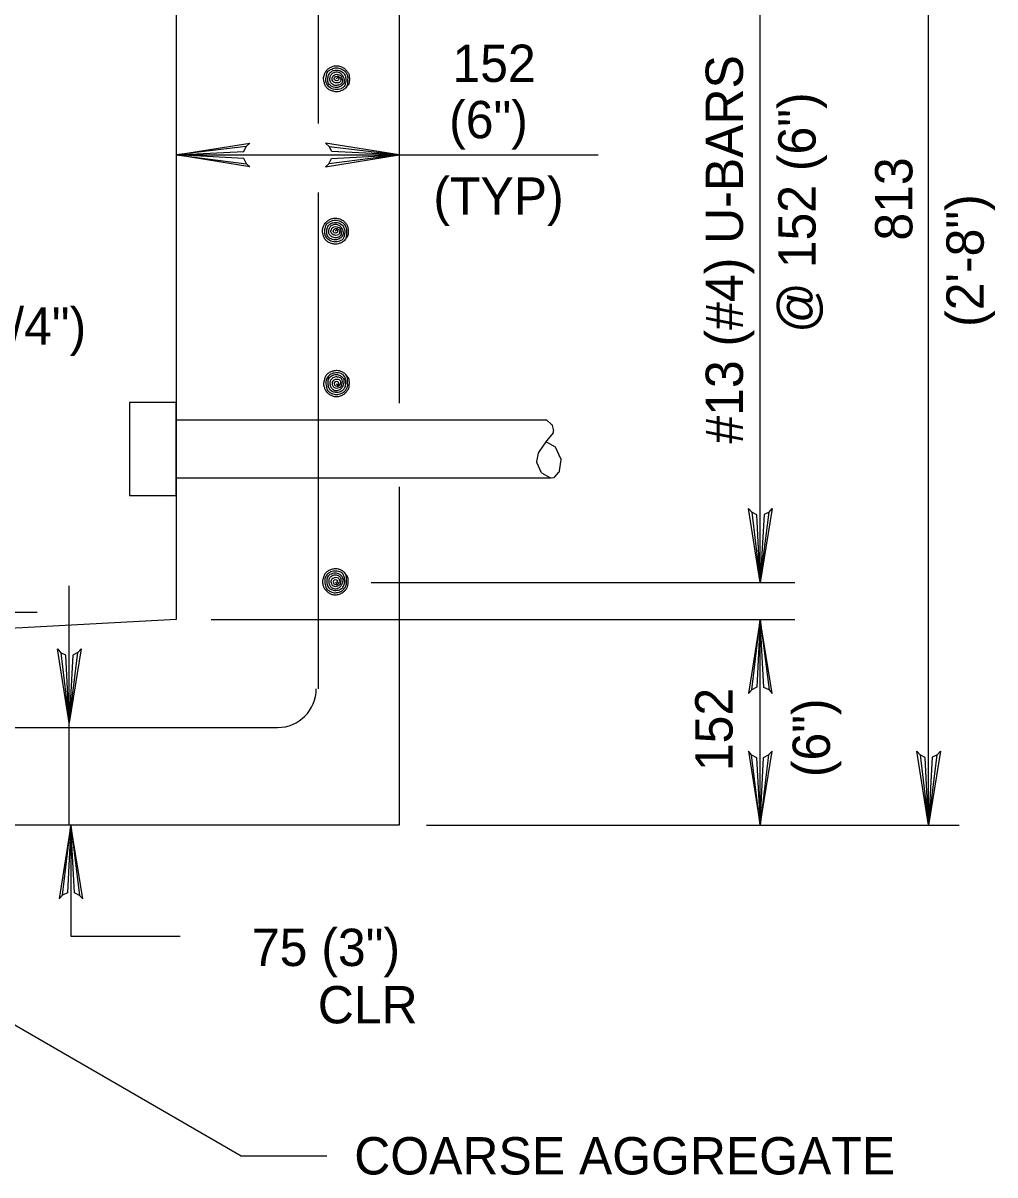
# Model space of a CAD drawing. Extents: x 638455 to 640199, y 298558 to 299152.
# Drawn here: x 638702.3 to 638789.8, y 298665.5 to 298769.2 of the extents above; entities that cross this region are included whole.
import ezdxf

# ---------------------------------------------------------------- set-up
doc = ezdxf.new("R2010")
doc.units = 0
for name, color, linetype in [('1', 7, 'Continuous'), ('2', 7, 'Continuous'), ('3', 7, 'Continuous')]:
    doc.layers.add(name, color=color, linetype=linetype)

msp = doc.modelspace()

# ---------------------------------------------------------------- linework, layer by layer
at = {"layer": '1'}
for p, q in [((638749.47, 298733.51), (638749.93, 298733.1)), ((638749.99, 298732.99), (638750.11, 298732.53)), ((638750.07, 298732.35), (638749.49, 298731.64)), ((638749.48, 298731.63), (638748.75, 298730.57)), ((638750.22, 298731.09), (638749.43, 298731.53)), ((638750.77, 298730.01), (638750.31, 298731)), ((638748.72, 298730.5), (638748.56, 298729.75)), ((638750.63, 298728.91), (638750.79, 298729.9)), ((638748.58, 298729.63), (638748.94, 298728.84)), ((638750.22, 298728.38), (638750.59, 298728.81)), ((638749.02, 298728.75), (638749.77, 298728.32)), ((638749.9, 298728.29), (638750.1, 298728.31))]:
    msp.add_line(p, q, dxfattribs=at)
for centre, start, end in [((638749.8, 298732.95), 13.5634, 48.2002), ((638749.91, 298732.48), 320.9795, 13.5634), ((638749.65, 298731.52), 140.9795, 145.5535), ((638750.13, 298730.91), 25.1893, 60.8708), ((638748.92, 298730.46), 145.5535, 167.862), ((638750.59, 298729.93), 351.1749, 25.1893), ((638748.76, 298729.71), 167.862, 204.893), ((638749.12, 298728.93), 204.893, 239.5523), ((638750.44, 298728.94), 319.4139, 351.1749), ((638749.87, 298728.49), 239.5523, 277.1288), ((638750.07, 298728.51), 277.1288, 319.4139)]:
    msp.add_arc(centre, 0.2, start, end, dxfattribs=at)
at = {"layer": '2'}
for p, q in [((638736.21, 298798.33), (638736.21, 298735)), ((638783.84, 298697.04), (638783.84, 298798.33)), ((638728.9, 298792.41), (638728.9, 298760.17)), ((638768.71, 298718.88), (638768.71, 298791.5)), ((638716.12, 298786.65), (638716.12, 298715.53)), ((638716.12, 298757.35), (638736.21, 298757.35)), ((638736.21, 298757.35), (638754.11, 298757.35)), ((638728.9, 298753.96), (638728.9, 298709.3)), ((638716.12, 298733.5), (638749.47, 298733.5)), ((638716.12, 298728.28), (638749.87, 298728.28)), ((638716.12, 298727.41), (638716.12, 298727.41)), ((638716.12, 298726.71), (638716.12, 298726.71)), ((638736.21, 298727.49), (638736.21, 298697.04)), ((638706.5, 298697.04), (638706.5, 298718.56)), ((638733.69, 298718.88), (638771.81, 298718.88)), ((638642.17, 298716.21), (638703.62, 298716.21)), ((638716.12, 298715.53), (638680.69, 298713.62)), ((638719.27, 298715.53), (638771.81, 298715.53)), ((638768.71, 298697.04), (638768.71, 298715.53)), ((638621.25, 298705.81), (638725.26, 298705.81)), ((638736.21, 298697.04), (638610.59, 298697.04)), ((638706.65, 298697.04), (638706.65, 298687.03)), ((638738.65, 298697.04), (638786.6, 298697.04)), ((638721.98, 298667.25), (638685.64, 298688.24)), ((638706.65, 298687.03), (638716.5, 298687.03)), ((638729.7, 298667.25), (638721.98, 298667.25))]:
    msp.add_line(p, q, dxfattribs=at)
for points in [[(638722.45, 298756.56), (638722.21, 298757.02), (638716.12, 298757.35), (638722.45, 298756.56), (638722.77, 298756.28), (638716.12, 298757.35), (638722.21, 298757.65), (638722.43, 298758.11), (638716.12, 298757.35), (638722.77, 298758.41), (638722.43, 298758.11)], [(638729.88, 298756.56), (638730.12, 298757.02), (638736.21, 298757.35), (638729.88, 298756.56), (638729.56, 298756.28), (638736.21, 298757.35), (638730.13, 298757.65), (638729.9, 298758.11), (638736.21, 298757.35), (638729.56, 298758.41), (638729.9, 298758.11)], [(638769.5, 298725.21), (638769.05, 298724.98), (638768.71, 298718.88), (638769.5, 298725.21), (638769.78, 298725.54), (638768.71, 298718.88), (638768.41, 298724.97), (638767.95, 298725.19), (638768.71, 298718.88), (638767.65, 298725.54), (638767.95, 298725.19)], [(638769.5, 298709.2), (638769.04, 298709.43), (638768.71, 298715.53), (638769.5, 298709.2), (638769.78, 298708.87), (638768.71, 298715.53), (638768.41, 298709.44), (638767.95, 298709.22), (638768.71, 298715.53), (638767.65, 298708.87), (638767.95, 298709.22)], [(638707.29, 298712.57), (638706.83, 298712.34), (638706.5, 298706.24), (638707.29, 298712.57), (638707.57, 298712.9), (638706.5, 298706.24), (638706.19, 298712.33), (638705.74, 298712.55), (638706.5, 298706.24), (638705.44, 298712.9), (638705.74, 298712.55)], [(638767.91, 298703.37), (638768.37, 298703.13), (638768.71, 298697.04), (638767.91, 298703.37), (638767.64, 298703.69), (638768.71, 298697.04), (638769.01, 298703.13), (638769.46, 298703.35), (638768.71, 298697.04), (638769.77, 298703.69), (638769.46, 298703.35)], [(638784.64, 298703.37), (638784.18, 298703.14), (638783.84, 298697.04), (638784.64, 298703.37), (638784.92, 298703.7), (638783.84, 298697.04), (638783.54, 298703.13), (638783.09, 298703.35), (638783.84, 298697.04), (638782.79, 298703.7), (638783.09, 298703.35)], [(638707.44, 298690.71), (638706.98, 298690.95), (638706.65, 298697.04), (638707.44, 298690.71), (638707.72, 298690.39), (638706.65, 298697.04), (638706.34, 298690.95), (638705.89, 298690.73), (638706.65, 298697.04), (638705.59, 298690.39), (638705.89, 298690.73)]]:
    msp.add_lwpolyline(points, dxfattribs=at)
msp.add_lwpolyline([(638716.12, 298726.71), (638716.12, 298735.07), (638711.93, 298735.07), (638711.93, 298726.71)], close=True, dxfattribs=at)
msp.add_arc((638725.26, 298709.3), 3.48, 270, 0, dxfattribs=at)
for points in [[(638730.57, 298764.2), (638730.63, 298764.32), (638730.72, 298764.3), (638730.74, 298764.12), (638730.58, 298764.02), (638730.38, 298764.12), (638730.39, 298764.3), (638730.5, 298764.42), (638730.72, 298764.43), (638730.87, 298764.32), (638730.95, 298764.13), (638730.84, 298763.88), (638730.6, 298763.83), (638730.33, 298763.9), (638730.18, 298764.08), (638730.2, 298764.36), (638730.34, 298764.54), (638730.58, 298764.61), (638730.79, 298764.57), (638730.97, 298764.46), (638731.05, 298764.27), (638731.09, 298764.03), (638731.04, 298763.81), (638730.83, 298763.67), (638730.5, 298763.6), (638730.16, 298763.74), (638729.98, 298763.99), (638729.98, 298764.32), (638730.1, 298764.6), (638730.34, 298764.78), (638730.72, 298764.81), (638730.99, 298764.66), (638731.16, 298764.39), (638731.25, 298764.12), (638731.21, 298763.79), (638730.99, 298763.56), (638730.67, 298763.43), (638730.17, 298763.5), (638729.85, 298763.78), (638729.79, 298764.17), (638729.85, 298764.54), (638730.07, 298764.84), (638730.37, 298764.96), (638730.83, 298764.95), (638731.19, 298764.74), (638731.36, 298764.43), (638731.41, 298764.11), (638731.37, 298763.83), (638731.26, 298763.52), (638730.97, 298763.31), (638730.49, 298763.24), (638730.06, 298763.36), (638729.74, 298763.66), (638729.61, 298764), (638729.65, 298764.44), (638729.79, 298764.86), (638730.03, 298765.03), (638730.45, 298765.19), (638730.89, 298765.12), (638731.2, 298764.98), (638731.44, 298764.71), (638731.56, 298764.42), (638731.56, 298764.12), (638731.55, 298763.79), (638731.47, 298763.48), (638731.32, 298763.31), (638731.08, 298763.16), (638730.84, 298763.07), (638730.6, 298763.03), (638730.29, 298763.08), (638729.98, 298763.18), (638729.72, 298763.37), (638729.54, 298763.62), (638729.45, 298763.93), (638729.4, 298764.23), (638729.47, 298764.57), (638729.59, 298764.84), (638729.81, 298765.09), (638730.07, 298765.26), (638730.34, 298765.36), (638730.65, 298765.37), (638731.01, 298765.28), (638731.32, 298765.09), (638731.5, 298764.89), (638731.66, 298764.64), (638731.71, 298764.38), (638731.72, 298764.08), (638731.66, 298763.74), (638731.56, 298763.59), (638731.36, 298763.37)], [(638730.47, 298750.49), (638730.53, 298750.6), (638730.62, 298750.59), (638730.64, 298750.41), (638730.48, 298750.31), (638730.28, 298750.41), (638730.29, 298750.59), (638730.4, 298750.7), (638730.62, 298750.72), (638730.77, 298750.6), (638730.85, 298750.42), (638730.73, 298750.17), (638730.49, 298750.11), (638730.23, 298750.19), (638730.08, 298750.36), (638730.1, 298750.65), (638730.23, 298750.83), (638730.48, 298750.9), (638730.69, 298750.85), (638730.87, 298750.75), (638730.95, 298750.56), (638730.99, 298750.32), (638730.93, 298750.1), (638730.73, 298749.95), (638730.41, 298749.89), (638730.06, 298750.04), (638729.88, 298750.28), (638729.88, 298750.6), (638729.99, 298750.89), (638730.23, 298751.07), (638730.62, 298751.1), (638730.89, 298750.94), (638731.06, 298750.68), (638731.16, 298750.41), (638731.11, 298750.08), (638730.89, 298749.85), (638730.57, 298749.71), (638730.07, 298749.79), (638729.75, 298750.07), (638729.69, 298750.45), (638729.75, 298750.83), (638729.97, 298751.13), (638730.27, 298751.25), (638730.73, 298751.24), (638731.09, 298751.03), (638731.26, 298750.72), (638731.31, 298750.4), (638731.27, 298750.11), (638731.16, 298749.81), (638730.87, 298749.6), (638730.39, 298749.53), (638729.96, 298749.65), (638729.64, 298749.95), (638729.51, 298750.29), (638729.54, 298750.74), (638729.69, 298751.15), (638729.93, 298751.32), (638730.35, 298751.48), (638730.79, 298751.41), (638731.1, 298751.27), (638731.34, 298751), (638731.46, 298750.71), (638731.46, 298750.41), (638731.45, 298750.08), (638731.37, 298749.77), (638731.22, 298749.6), (638730.98, 298749.45), (638730.73, 298749.36), (638730.49, 298749.32), (638730.19, 298749.36), (638729.88, 298749.46), (638729.62, 298749.66), (638729.44, 298749.91), (638729.35, 298750.22), (638729.3, 298750.52), (638729.37, 298750.85), (638729.49, 298751.13), (638729.71, 298751.38), (638729.97, 298751.55), (638730.23, 298751.64), (638730.55, 298751.65), (638730.91, 298751.57), (638731.22, 298751.38), (638731.41, 298751.18), (638731.56, 298750.93), (638731.61, 298750.67), (638731.62, 298750.36), (638731.56, 298750.04), (638731.46, 298749.88), (638731.26, 298749.66)], [(638730.57, 298736.77), (638730.63, 298736.66), (638730.72, 298736.67), (638730.74, 298736.86), (638730.58, 298736.95), (638730.38, 298736.86), (638730.39, 298736.67), (638730.5, 298736.56), (638730.72, 298736.54), (638730.87, 298736.66), (638730.95, 298736.85), (638730.84, 298737.1), (638730.6, 298737.15), (638730.33, 298737.07), (638730.18, 298736.9), (638730.2, 298736.62), (638730.34, 298736.43), (638730.58, 298736.37), (638730.79, 298736.41), (638730.97, 298736.52), (638731.05, 298736.7), (638731.09, 298736.95), (638731.04, 298737.17), (638730.83, 298737.31), (638730.5, 298737.37), (638730.16, 298737.23), (638729.98, 298736.99), (638729.98, 298736.66), (638730.1, 298736.38), (638730.34, 298736.19), (638730.72, 298736.17), (638730.99, 298736.32), (638731.16, 298736.58), (638731.25, 298736.86), (638731.21, 298737.19), (638730.99, 298737.42), (638730.67, 298737.55), (638730.17, 298737.47), (638729.85, 298737.2), (638729.79, 298736.81), (638729.85, 298736.43), (638730.07, 298736.14), (638730.37, 298736.02), (638730.83, 298736.03), (638731.19, 298736.23), (638731.36, 298736.54), (638731.41, 298736.87), (638731.37, 298737.15), (638731.26, 298737.45), (638730.97, 298737.67), (638730.49, 298737.74), (638730.06, 298737.61), (638729.74, 298737.32), (638729.61, 298736.97), (638729.65, 298736.53), (638729.79, 298736.12), (638730.03, 298735.94), (638730.45, 298735.79), (638730.89, 298735.85), (638731.2, 298736), (638731.44, 298736.27), (638731.56, 298736.55), (638731.56, 298736.86), (638731.55, 298737.19), (638731.47, 298737.49), (638731.32, 298737.67), (638731.08, 298737.82), (638730.84, 298737.91), (638730.6, 298737.94), (638730.29, 298737.9), (638729.98, 298737.8), (638729.72, 298737.61), (638729.54, 298737.36), (638729.45, 298737.04), (638729.4, 298736.75), (638729.47, 298736.41), (638729.59, 298736.14), (638729.81, 298735.89), (638730.07, 298735.72), (638730.34, 298735.62), (638730.65, 298735.61), (638731.01, 298735.7), (638731.32, 298735.89), (638731.5, 298736.08), (638731.66, 298736.33), (638731.71, 298736.6), (638731.72, 298736.9), (638731.66, 298737.23), (638731.56, 298737.38), (638731.36, 298737.61)], [(638730.47, 298718.94), (638730.53, 298718.82), (638730.62, 298718.83), (638730.64, 298719.01), (638730.48, 298719.11), (638730.28, 298719.01), (638730.29, 298718.83), (638730.4, 298718.72), (638730.62, 298718.7), (638730.77, 298718.82), (638730.85, 298719), (638730.73, 298719.25), (638730.49, 298719.31), (638730.23, 298719.23), (638730.08, 298719.06), (638730.1, 298718.77), (638730.23, 298718.59), (638730.48, 298718.52), (638730.69, 298718.57), (638730.87, 298718.68), (638730.95, 298718.86), (638730.99, 298719.1), (638730.93, 298719.33), (638730.73, 298719.47), (638730.41, 298719.53), (638730.06, 298719.39), (638729.88, 298719.15), (638729.88, 298718.82), (638729.99, 298718.54), (638730.23, 298718.35), (638730.62, 298718.33), (638730.89, 298718.48), (638731.06, 298718.74), (638731.16, 298719.01), (638731.11, 298719.34), (638730.89, 298719.58), (638730.57, 298719.71), (638730.07, 298719.63), (638729.75, 298719.35), (638729.69, 298718.97), (638729.75, 298718.59), (638729.97, 298718.3), (638730.27, 298718.18), (638730.73, 298718.19), (638731.09, 298718.39), (638731.26, 298718.7), (638731.31, 298719.03), (638731.27, 298719.31), (638731.16, 298719.61), (638730.87, 298719.83), (638730.39, 298719.89), (638729.96, 298719.77), (638729.64, 298719.48), (638729.51, 298719.13), (638729.54, 298718.69), (638729.69, 298718.27), (638729.93, 298718.1), (638730.35, 298717.95), (638730.79, 298718.01), (638731.1, 298718.15), (638731.34, 298718.43), (638731.46, 298718.71), (638731.46, 298719.01), (638731.45, 298719.34), (638731.37, 298719.65), (638731.22, 298719.83), (638730.98, 298719.98), (638730.73, 298720.07), (638730.49, 298720.1), (638730.19, 298720.06), (638729.88, 298719.96), (638729.62, 298719.76), (638729.44, 298719.51), (638729.35, 298719.2), (638729.3, 298718.91), (638729.37, 298718.57), (638729.49, 298718.3), (638729.71, 298718.05), (638729.97, 298717.88), (638730.23, 298717.78), (638730.55, 298717.77), (638730.91, 298717.86), (638731.22, 298718.05), (638731.41, 298718.24), (638731.56, 298718.49), (638731.61, 298718.75), (638731.62, 298719.06), (638731.56, 298719.39), (638731.46, 298719.54), (638731.26, 298719.76)]]:
    msp.add_spline(points, degree=3, dxfattribs=at)

# ---------------------------------------------------------------- texts
at = {"layer": '3'}
for s, p in [('152', (638741, 298763.92)), ('(6")', (638740.7, 298758.85)), ('(TYP)', (638739.28, 298751.97)), ('6 (1/4")', (638693.45, 298740.26)), ('75 (3")', (638722.95, 298684.35)), ('CLR', (638728.88, 298679.19)), ('COARSE AGGREGATE', (638732.16, 298665.59))]:
    msp.add_text(s, height=3.36, dxfattribs=at).set_placement(p)
for s, p in [('#13 (#4) U-BARS', (638767.15, 298731.37)), ('@ 152 (6")', (638773.69, 298741.34)), ('813', (638782.4, 298749.64)), ('(2\'-8")', (638788.82, 298741.87)), ('152', (638766.21, 298701.89)), ('(6")', (638774.98, 298701.35))]:
    msp.add_text(s, height=3.36, rotation=90, dxfattribs=at).set_placement(p)

doc.saveas('drawing.dxf')
